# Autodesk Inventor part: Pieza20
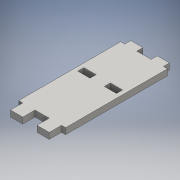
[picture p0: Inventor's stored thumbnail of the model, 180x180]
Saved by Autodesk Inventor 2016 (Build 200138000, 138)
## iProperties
Created: 2016-06
Part Number: Pieza20
Material: Genérico
Document SubType Name: Modeling
Designer: adm
Density: 1 g/cm^3
Appearance: Valor por defecto
Author: adm
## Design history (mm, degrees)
sketch "Boceto1"
  geometry: L1 (11.5, 25)-(11.5, -25); L2 (-11.5, -25)-(-11.5, 25); L3 (-11.5, 25)-(11.5, -25); L4 (11.5, 25)-(-11.5, -25); L5 (3.5, 25)-(3.5, 28); L6 (3.5, 28)-(9.5, 28); L7 (9.5, 28)-(9.5, 25); L8 (-3.5, 25)-(-3.5, 28); L9 (-3.5, 28)-(-9.5, 28); L10 (-9.5, 28)-(-9.5, 25); L11 (-11.5, 25)-(-9.5, 25); L12 (-3.5, 25)-(3.5, 25); L13 (9.5, 25)-(11.5, 25); L14 (9.5, -31)-(9.5, -25); L15 (3.5, -31)-(9.5, -31); L16 (-3.5, -25)-(-3.5, -31); L17 (-3.5, -31)-(-9.5, -31); L18 (-9.5, -31)-(-9.5, -25); L19 (3.5, -25)-(3.5, -31); L20 (-9.5, -25)-(-11.5, -25); L21 (11.5, -25)-(9.5, -25); L22 (3.5, -25)-(-3.5, -25); 1 further point
  constraints: 44 end point, 11 parallel, 5 horizontal, 4 vertical, 3 perpendicular, 2 horizontal alignment, 2 midpoint
  dimensions: "d0" = 50 distance of L1.start L1.end; "d1" = 23 distance of L1.end L2.start; "d2" = 3 distance of L6.end L7.end; "d3" = 2 distance between parallel lines of L7 L1; "d4" = 6 distance of L5.end L6.end; "d13" = 6 distance of L16.start L16.end; "d14" = 6 distance of L19.start L15.start; "d15" = 7 distance between parallel lines of L8 L5; "d16" = 6 distance between parallel lines of L10 L8; "d17" = 2 distance between parallel lines of L14 L1; "d18" = 6 distance between parallel lines of L14 L19; "d19" = 7 distance between parallel lines of L19 L16
extrude "Extrusión1" new body sketch "Boceto1" distance "d5" = 3; taper "d6" = 0 deg
sketch "Boceto2"
  geometry: L1 (-9.5, 5)-(-3.5, 5); L2 (-3.5, 5)-(-3.5, 2); L3 (-3.5, 2)-(-9.5, 2); L4 (-9.5, 2)-(-9.5, 5); L5 (-11.5, 25)-(-11.5, -25) reference; L6 (3.5, 25)-(-3.5, 25) reference; L7 (0, 0)-(0, 10.364); L8 (9.5, 5)-(3.5, 5); L9 (3.5, 5)-(3.5, 2); L10 (3.5, 2)-(9.5, 2); L11 (9.5, 2)-(9.5, 5)
  constraints: 18 end point, 4 symmetric about line, 2 parallel, 1 horizontal, 1 perpendicular, 1 vertical
  dimensions: "d7" = 6 distance of L1.start L1.end; "d8" = 3 distance of L1.end L2.end; "d9" = 2 distance between parallel lines of L5 L4; "d10" = 20 distance between parallel lines of L1 L6
extrude "Extrusión2" cut sketch "Boceto2" distance "d11" = 10; taper "d12" = 0 deg
node "Sólido1"
